(* Logix 5000 project; controller AMCI_5034_PTO_AM_Sample vendor 1 type 14 code 190 rev 37.11; software revision 37.00; part 2 of 3 *)
(* tags used below, declared in another part *)
   Move_type_0_Absolute_1_Relative : BOOL;   // 0=absolute 1=relative
   _0_normal_1_S_Curve_Acceleration : BOOL;
   _0_Triangular_1_Trapezoidal_S_Curve : BOOL;
   TargetVelocity : DINT;
   Acceleration : DINT;
   Deceleration : DINT;
   PC : BOOL;   // set when process complete
   motion_occurring : BOOL;
   Internal_Enable : BOOL;   // set when driver ready to receive motion command
(* AMCI_5034_PTO_AM_MAM, continued *)

ROUTINE Logic   (* ladder *)
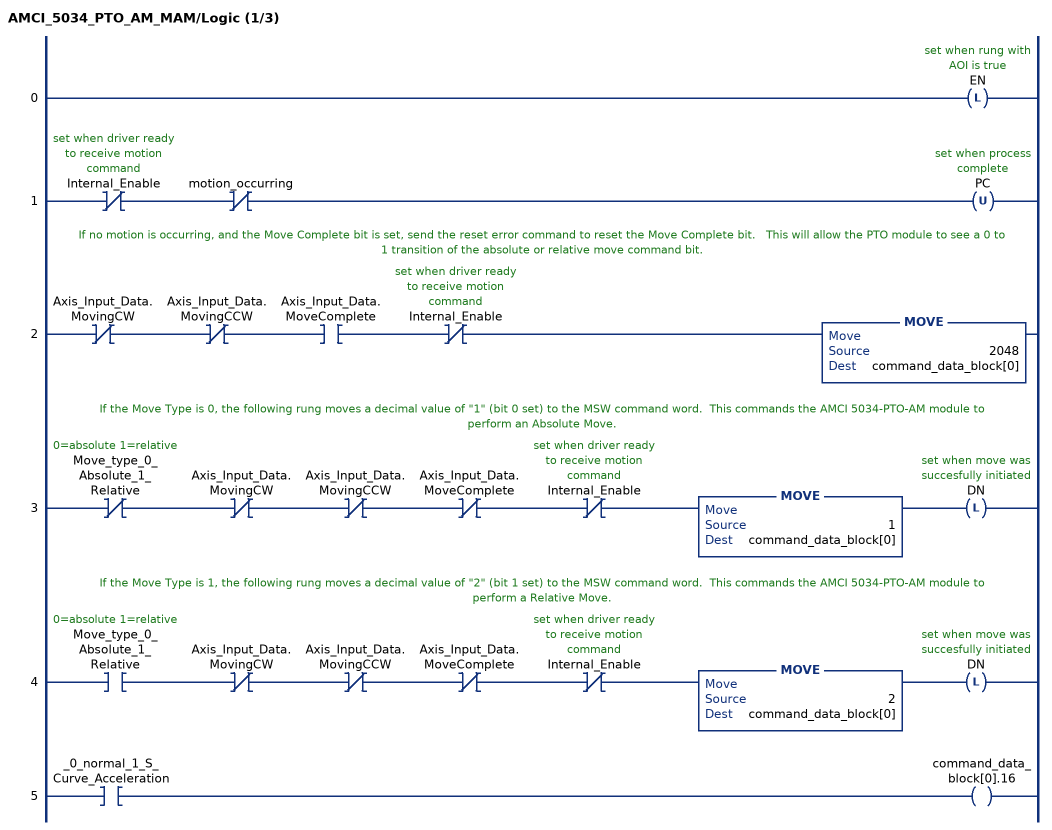
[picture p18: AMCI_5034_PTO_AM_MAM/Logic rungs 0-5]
   0: OTL(EN);
   1: XIO(Internal_Enable)XIO(motion_occurring)OTU(PC);
   // If no motion is occurring, and the Move Complete bit is set, send the reset error command to reset the Move Complete bit.   This will allow the PTO module to see a 0 to 1 transition of the absolute or relative move command bit.
   2: XIO(Axis_Input_Data.MovingCW)XIO(Axis_Input_Data.MovingCCW)XIC(Axis_Input_Data.MoveComplete)XIO(Internal_Enable)MOVE(2048,command_data_block[0]);
   // If the Move Type is 0, the following rung moves a decimal value of "1" (bit 0 set) to the MSW command word.  This commands the AMCI 5034-PTO-AM module to perform an Absolute Move.
   3: XIO(Move_type_0_Absolute_1_Relative)XIO(Axis_Input_Data.MovingCW)XIO(Axis_Input_Data.MovingCCW)XIO(Axis_Input_Data.MoveComplete)XIO(Internal_Enable)MOVE(1,command_data_block[0])OTL(DN);
   // If the Move Type is 1, the following rung moves a decimal value of "2" (bit 1 set) to the MSW command word.  This commands the AMCI 5034-PTO-AM module to perform a Relative Move.
   4: XIC(Move_type_0_Absolute_1_Relative)XIO(Axis_Input_Data.MovingCW)XIO(Axis_Input_Data.MovingCCW)XIO(Axis_Input_Data.MoveComplete)XIO(Internal_Enable)MOVE(2,command_data_block[0])OTL(DN);
   5: XIC(_0_normal_1_S_Curve_Acceleration)OTE(command_data_block[0].16);
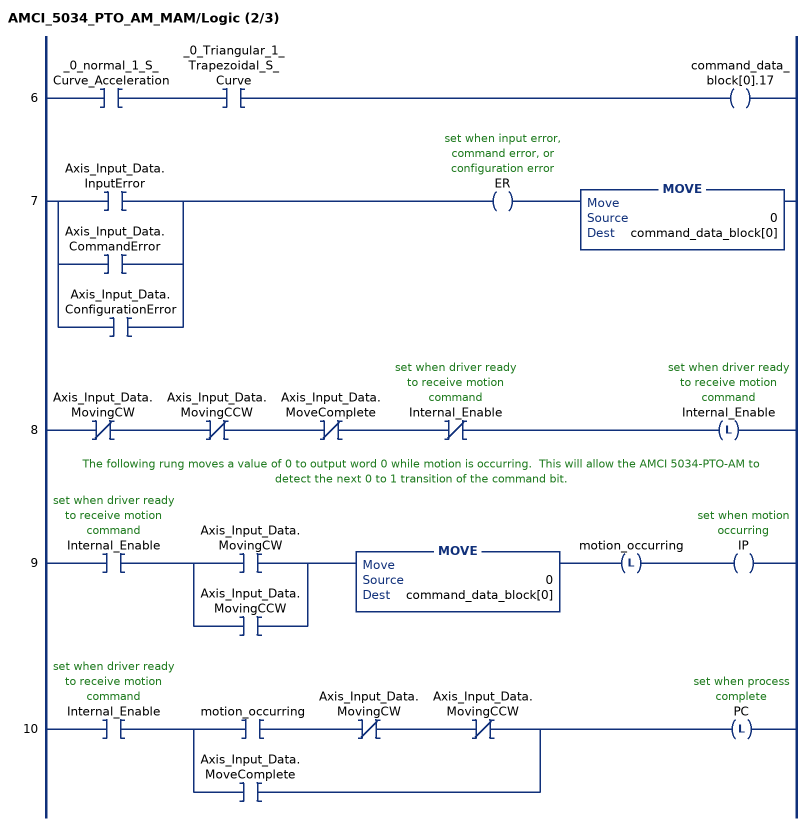
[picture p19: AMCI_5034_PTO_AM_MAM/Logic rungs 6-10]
   6: XIC(_0_normal_1_S_Curve_Acceleration)XIC(_0_Triangular_1_Trapezoidal_S_Curve)OTE(command_data_block[0].17);
   7: [XIC(Axis_Input_Data.InputError) ,XIC(Axis_Input_Data.CommandError) ,XIC(Axis_Input_Data.ConfigurationError) ]OTE(ER)MOVE(0,command_data_block[0]);
   8: XIO(Axis_Input_Data.MovingCW)XIO(Axis_Input_Data.MovingCCW)XIO(Axis_Input_Data.MoveComplete)XIO(Internal_Enable)OTL(Internal_Enable);
   // The following rung moves a value of 0 to output word 0 while motion is occurring.  This will allow the AMCI 5034-PTO-AM to detect the next 0 to 1 transition of the command bit.
   9: XIC(Internal_Enable)[XIC(Axis_Input_Data.MovingCW) ,XIC(Axis_Input_Data.MovingCCW) ]MOVE(0,command_data_block[0])OTL(motion_occurring)OTE(IP);
   10: XIC(Internal_Enable)[XIC(motion_occurring) XIO(Axis_Input_Data.MovingCW) XIO(Axis_Input_Data.MovingCCW) ,XIC(Axis_Input_Data.MoveComplete) ]OTL(PC);
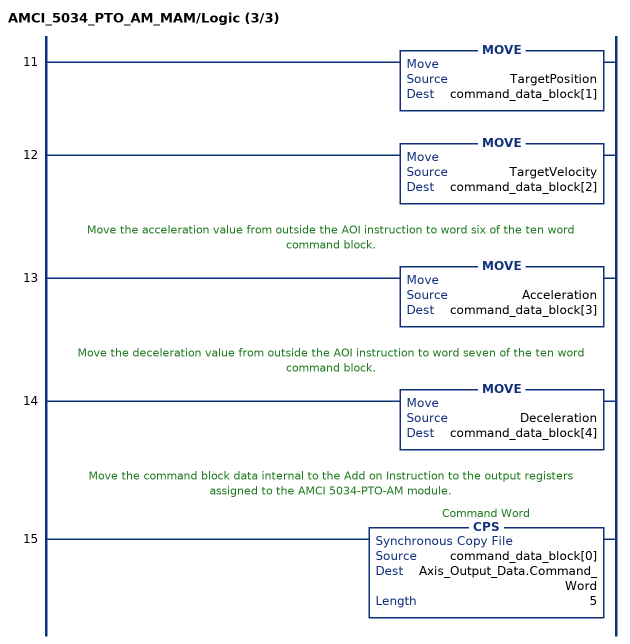
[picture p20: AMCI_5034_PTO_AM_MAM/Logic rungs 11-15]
   11: MOVE(TargetPosition,command_data_block[1]);
   12: MOVE(TargetVelocity,command_data_block[2]);
   // Move the acceleration value from outside the AOI instruction to word six of the ten word command block.
   13: MOVE(Acceleration,command_data_block[3]);
   // Move the deceleration value from outside the AOI instruction to word seven of the ten word command block.
   14: MOVE(Deceleration,command_data_block[4]);
   // Move the command block data internal to the Add on Instruction to the output registers assigned to the AMCI 5034-PTO-AM module.
   15: CPS(command_data_block[0],Axis_Output_Data.Command_Word,5);
END_ROUTINE
END_ADD_ON_INSTRUCTION

ADD_ON_INSTRUCTION AMCI_5034_PTO_AM_MRP   (* revision 1.0, vendor AMCI, ExecuteEnableInFalse *)
// AMCI Preset Position
// Revision note:
// 10/01/2025 Intial release
// Help:
// MOTION REDEFINE POSITION: Sets the Current Motor Position to the value in the Target Position field of the AOI.  This command will also reset the Position Invalid status bit.
// AXIS INPUT DATA:  Input data from the AMCI 5034-PTO-AM.   Uses the AMCI_5034_PTO_Input_Data User Defined Data Type.
// AXIS OUTPUT DATA; Output data from the AOI to the AMCI 5034-PTO-AM.    Uses the AMCI_5034_PTO_Output_Data User Defined Data Type.
// TARGET POSITION: Position to which the Motor Position is to be set.
// SAVE_IN_FLASH_0_NO_1_YES:   Saves the offset in the flash memory.    Only used on the SVXXXE2 units.  Must be zero on all other units.
// EN (Enable) Set when rung is true, Reset when rung is false
// DN (Done) Set when command is sent to the motion device.  Reset when the rung is false.
// ER (Error) Set when a command or input error failed to clear.  Reset when the rung is false.
VAR_IN_OUT
   Axis_Input_Data : AMCI_5034_PTO_AM_Input_Data; {required}
   Axis_Output_Data : AMCI_5034_PTO_AM_Output_Data; {required}
END_VAR
VAR_INPUT
   TargetPosition : DINT; {required}
END_VAR
VAR_OUTPUT
   EN : BOOL; {visible}   // set when rung with AOI is true
   DN : BOOL; {access Read Only, visible}   // set when preset motor position command sent to motion axis
   ER : BOOL; {access Read Only, visible}   // set when input, command, or configuraiton error
END_VAR
VAR
   command_data_block : DINT[5];
        [0]   // Command Bits MSW
        [1]   // Target Position
        [2]   // Upper Target Position
        [3]   // Lower Target Position
        [4]   // Upper Programmed Speed
END_VAR

ROUTINE EnableInFalse   (* ladder *)
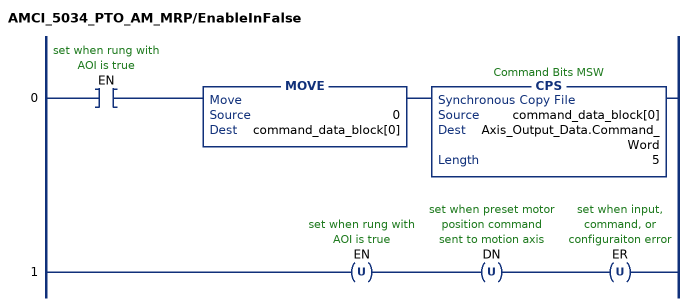
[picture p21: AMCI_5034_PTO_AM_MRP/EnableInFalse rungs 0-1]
   0: XIC(EN)MOVE(0,command_data_block[0])CPS(command_data_block[0],Axis_Output_Data.Command_Word,5);
   1: OTU(EN)OTU(DN)OTU(ER);
END_ROUTINE

ROUTINE Logic   (* ladder *)
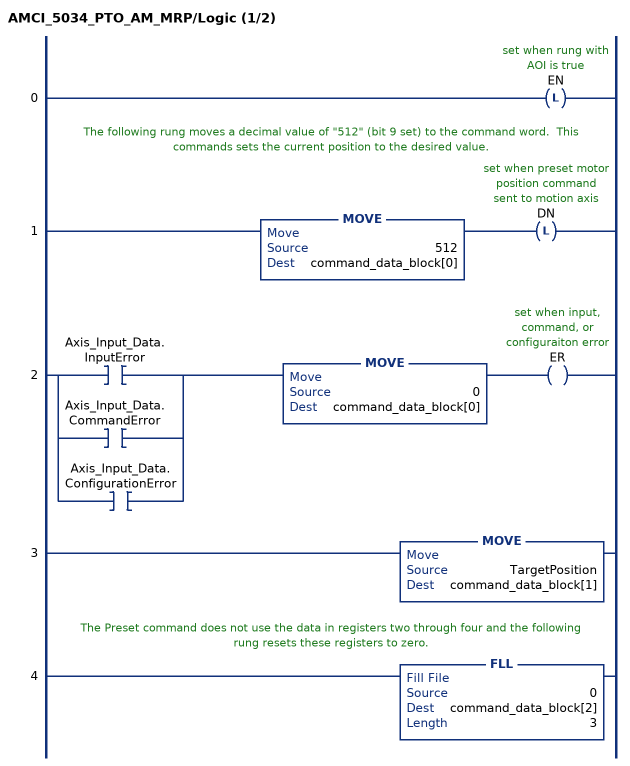
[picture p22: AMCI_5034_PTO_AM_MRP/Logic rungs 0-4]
   0: OTL(EN);
   // The following rung moves a decimal value of "512" (bit 9 set) to the command word.  This commands sets the current position to the desired value.
   1: MOVE(512,command_data_block[0])OTL(DN);
   2: [XIC(Axis_Input_Data.InputError) ,XIC(Axis_Input_Data.CommandError) ,XIC(Axis_Input_Data.ConfigurationError) ]MOVE(0,command_data_block[0])OTE(ER);
   3: MOVE(TargetPosition,command_data_block[1]);
   // The Preset command does not use the data in registers two through four and the following rung resets these registers to zero.
   4: FLL(0,command_data_block[2],3);
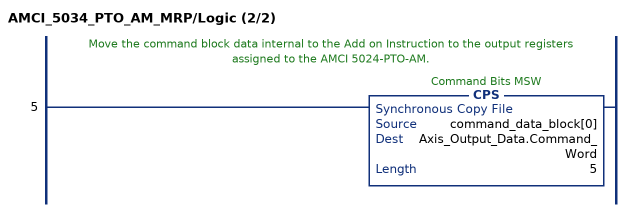
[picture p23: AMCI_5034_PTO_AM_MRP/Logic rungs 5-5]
   // Move the command block data internal to the Add on Instruction to the output registers assigned to the AMCI 5024-PTO-AM.
   5: CPS(command_data_block[0],Axis_Output_Data.Command_Word,5);
END_ROUTINE
END_ADD_ON_INSTRUCTION

ADD_ON_INSTRUCTION AMCI_5034_PTO_AM_Preset_Encoder   (* revision 1.0, vendor AMCI, ExecuteEnableInFalse *)
// Revision note:
// 10/01/2025 initial release
// Help:
// PRESET_ENCODER: Preset Encoder Position to the Target Position value.
// AXIS INPUT DATA:  Input data from the AMCI 5034-PTO-AM.   Uses the AMCI_5034_PTO_Input_Data User Defined Data Type.
// AXIS OUTPUT DATA; Output data from the AOI to the AMCI 5034-PTO-AM.    Uses the AMCI_5034_PTO_Output_Data User Defined Data Type.
// TARGETPOSITION: Position to which the Encoder Position is to be set.
// EN (Enable) Set when rung is true, Reset when rung is false
// DN (Done) Set when command is sent to the motion device.  Reset when the rung is false.
// ER (Error) Set when a command or input error failed to clear.  Reset when the rung is false.
VAR_IN_OUT
   Axis_Input_Data : AMCI_5034_PTO_AM_Input_Data; {required}
   Axis_Output_Data : AMCI_5034_PTO_AM_Output_Data; {required}
END_VAR
VAR_INPUT
   TargetPosition : DINT; {required}
END_VAR
VAR_OUTPUT
   EN : BOOL; {visible}   // set when rung with AOI is true
   DN : BOOL; {access Read Only, visible}   // set when preset motor position command sent to motion axis
   ER : BOOL; {access Read Only, visible}   // set when input, command, or configuraiton error
END_VAR
VAR
   command_data_block : DINT[5];
        [0]   // Command Bits MSW
        [1]   // Target Position
        [2]   // Upper Target Position
        [3]   // Lower Target Position
        [4]   // Upper Programmed Speed
END_VAR

ROUTINE EnableInFalse   (* ladder *)
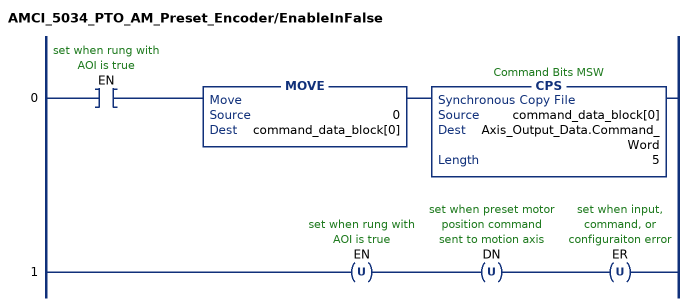
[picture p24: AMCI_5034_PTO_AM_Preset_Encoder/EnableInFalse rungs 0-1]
   0: XIC(EN)MOVE(0,command_data_block[0])CPS(command_data_block[0],Axis_Output_Data.Command_Word,5);
   1: OTU(EN)OTU(DN)OTU(ER);
END_ROUTINE

ROUTINE Logic   (* ladder *)
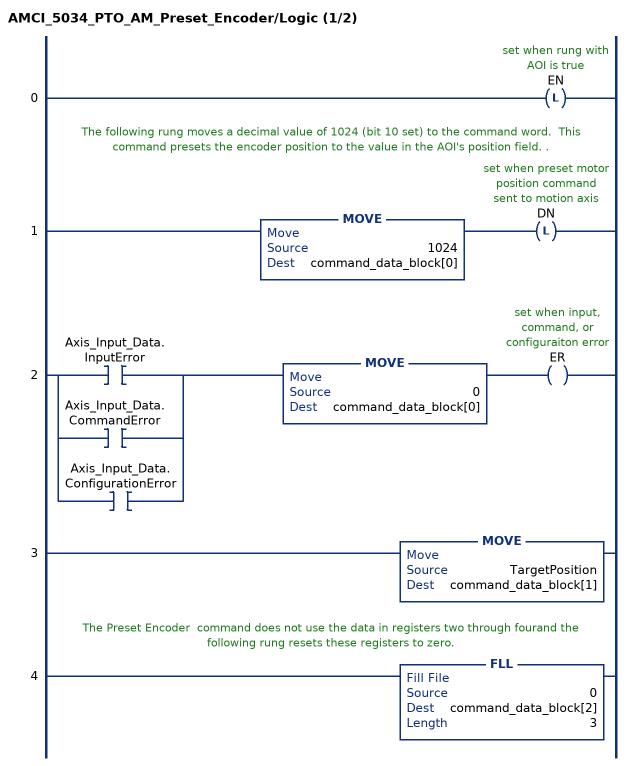
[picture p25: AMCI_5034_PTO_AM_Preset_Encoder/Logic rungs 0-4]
   0: OTL(EN);
   // The following rung moves a decimal value of 1024 (bit 10 set) to the command word.  This command presets the encoder position to the value in the AOI's position field. .
   1: MOVE(1024,command_data_block[0])OTL(DN);
   2: [XIC(Axis_Input_Data.InputError) ,XIC(Axis_Input_Data.CommandError) ,XIC(Axis_Input_Data.ConfigurationError) ]MOVE(0,command_data_block[0])OTE(ER);
   3: MOVE(TargetPosition,command_data_block[1]);
   // The Preset Encoder  command does not use the data in registers two through fourand the following rung resets these registers to zero.
   4: FLL(0,command_data_block[2],3);
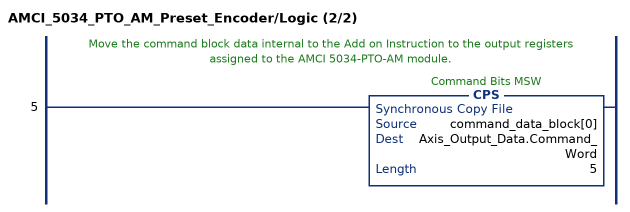
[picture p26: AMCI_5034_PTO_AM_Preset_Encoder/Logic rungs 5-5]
   // Move the command block data internal to the Add on Instruction to the output registers assigned to the AMCI 5034-PTO-AM module.
   5: CPS(command_data_block[0],Axis_Output_Data.Command_Word,5);
END_ROUTINE
END_ADD_ON_INSTRUCTION

ADD_ON_INSTRUCTION AMCI_5034_PTO_AM_Prog_Min_Reg_Dist   (* revision 1.0, vendor AMCI, ExecuteEnableInFalse *)
// AMCI Program Minimum Registration Distance
// Revision note:
// 10/01/2025 Intial release
// Help:
// AXIS INPUT DATA:  Input data from the AMCI 5034-PTO-AM.   Uses the AMCI_5034_PTO_Input_Data User Defined Data Type.
// AXIS OUTPUT DATA; Output data from the AOI to the AMCI 5034-PTO-AM.    Uses the AMCI_5034_PTO_Output_Data User Defined Data Type.
// TARGETPOSITION: The number of steps that must be output by the PTO module before it will start looking for the registration input.
// EN (Enable) Set when rung is true, Reset when rung is false
// DN (Done) Set when command is sent to the PTO module.  Reset when the rung is false.
// ER (Error) Set when a command, input error, or configuation error.   Reset when the rung is false.
VAR_IN_OUT
   Axis_Input_Data : AMCI_5034_PTO_AM_Input_Data; {required}
   Axis_Output_Data : AMCI_5034_PTO_AM_Output_Data; {required}
END_VAR
VAR_INPUT
   Minimum_Registration_Distance : DINT; {required}
END_VAR
VAR_OUTPUT
   EN : BOOL; {visible}   // set when rung with AOI is true
   DN : BOOL; {access Read Only, visible}   // set when mnimum registration distance has been programmed
   ER : BOOL; {access Read Only, visible}   // set when input, command, or configuraiton error
END_VAR
VAR
   command_data_block : DINT[5];
        [0]   // Command Bits MSW
        [1]   // Target Position
        [2]   // Upper Target Position
        [3]   // Lower Target Position
        [4]   // Upper Programmed Speed
END_VAR

ROUTINE EnableInFalse   (* ladder *)
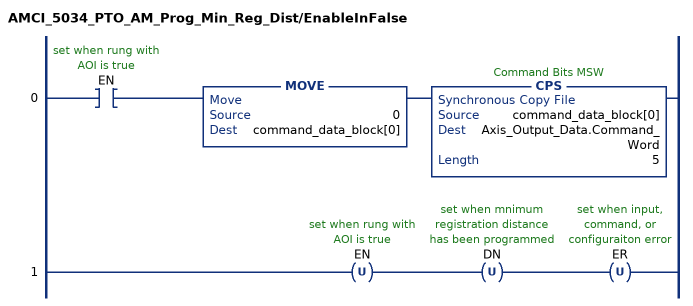
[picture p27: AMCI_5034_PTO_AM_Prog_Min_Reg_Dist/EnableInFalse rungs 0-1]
   0: XIC(EN)MOVE(0,command_data_block[0])CPS(command_data_block[0],Axis_Output_Data.Command_Word,5);
   1: OTU(EN)OTU(DN)OTU(ER);
END_ROUTINE

ROUTINE Logic   (* ladder *)
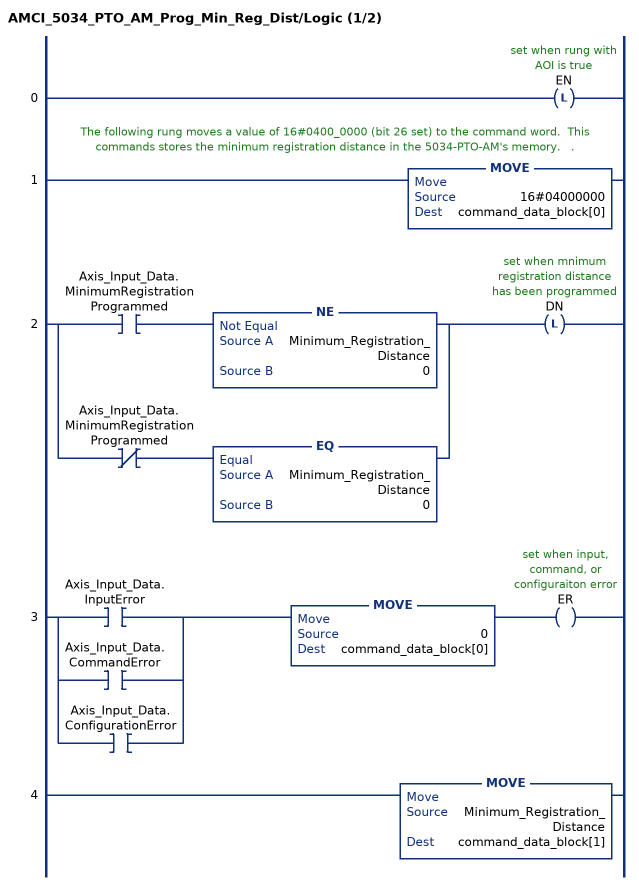
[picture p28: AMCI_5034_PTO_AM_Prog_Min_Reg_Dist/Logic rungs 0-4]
   0: OTL(EN);
   // The following rung moves a value of 16#0400_0000 (bit 26 set) to the command word.  This commands stores the minimum registration distance in the 5034-PTO-AM's memory.   .
   1: MOVE(16#04000000,command_data_block[0]);
   2: [XIC(Axis_Input_Data.MinimumRegistrationProgrammed) NE(Minimum_Registration_Distance,0) ,XIO(Axis_Input_Data.MinimumRegistrationProgrammed) EQ(Minimum_Registration_Distance,0) ]OTL(DN);
   3: [XIC(Axis_Input_Data.InputError) ,XIC(Axis_Input_Data.CommandError) ,XIC(Axis_Input_Data.ConfigurationError) ]MOVE(0,command_data_block[0])OTE(ER);
   4: MOVE(Minimum_Registration_Distance,command_data_block[1]);
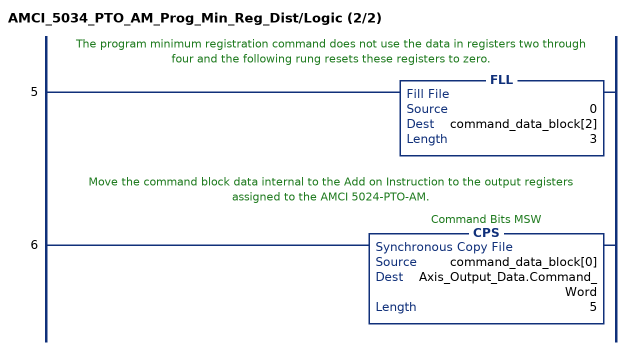
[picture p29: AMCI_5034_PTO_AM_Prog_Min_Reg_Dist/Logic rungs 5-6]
   // The program minimum registration command does not use the data in registers two through four and the following rung resets these registers to zero.
   5: FLL(0,command_data_block[2],3);
   // Move the command block data internal to the Add on Instruction to the output registers assigned to the AMCI 5024-PTO-AM.
   6: CPS(command_data_block[0],Axis_Output_Data.Command_Word,5);
END_ROUTINE
END_ADD_ON_INSTRUCTION

ADD_ON_INSTRUCTION AMCI_5034_PTO_AM_Program_Blend_Move   (* revision 0.0, ExecuteEnableInFalse *)
// Revision note:
// 10/01/2025 initial release
// Help:
// Programs up to 16 segments of a blend move.
// AXIS INPUT DATA:  Input data from the AMCI 5034-PTO-AM.   Uses the AMCI_5034_PTO_Input_Data User Defined Data Type.
// AXIS OUTPUT DATA; Output data from the AOI to the AMCI 5034-PTO-AM.    Uses the AMCI_5034_PTO_Output_Data User Defined Data Type.
// NUMBER_OF_SEGMENTS: Defines the number of segments in the blend move.   Range of 2 to 16.
// FINAL_MOVE_DECELERATION: Defines the deceleration from the last sement to rest.
// SEGMENT_X_DISTANCE: The relative move distance of each of the segments.
// SEGMENT_X_TARGETVELOCITY: The speed of the segment.
// SEGMENT_X_ ACCELERATION_DECELERATION: The value to accelerate or decelerate from one segment to the next segment.
// EN: Set whe the rung with the Program Blend AOI is receiving power.
// ER: Set when there is a Command Error, Configuation Error, Input Error, or Invalid Profile Error.
// IP: Set when each segment of the blend profile is being programmed.
// BLEND_MOVE_PROGRAMMED: Set when all of the segments of the blend profile have been programmed.
VAR_IN_OUT
   Axis_Input_Data : AMCI_5034_PTO_AM_Input_Data; {required}
   Axis_Output_Data : AMCI_5034_PTO_AM_Output_Data; {required}
END_VAR
VAR_INPUT
   Number_of_Segments : DINT; {required}
   Acceleration_Type_segments_1_to_16 : DINT;
   Final_Move_Deceleration : DINT; {required}
   Segment_1_Distance : DINT; {required}
   Segment_1_TargetVelocity : DINT; {required}
   Segment_1_Acceleration_Deceleration : DINT; {required}
   Segment_2_Distance : DINT; {required}
   Segment_2_TargetVelocity : DINT; {required}
   Segment_2_Acceleration_Deceleration : DINT; {required}
   Segment_3_Distance : DINT; {required}
   Segment_3_TargetVelocity : DINT; {required}
   Segment_3_Acceleration_Deceleration : DINT; {required}
   Segment_4_Distance : DINT; {required}
   Segment_4_TargetVelocity : DINT; {required}
   Segment_4_Acceleration_Deceleration : DINT; {required}
   Segment_5_Distance : DINT; {required}
   Segment_5_TargetVelocity : DINT; {required}
   Segment_5_Acceleration_Deceleration : DINT; {required}
   Segment_6_Distance : DINT; {required}
   Segment_6_TargetVelocity : DINT; {required}
   Segment_6_Acceleration_Deceleration : DINT; {required}
   Segment_7_Distance : DINT; {required}
   Segment_7_TargetVelocity : DINT; {required}
   Segment_7_Acceleration_Deceleration : DINT; {required}
   Segment_8_Distance : DINT; {required}
   Segment_8_TargetVelocity : DINT; {required}
   Segment_8_Acceleration_Deceleration : DINT; {required}
   Segment_9_Distance : DINT; {required}
   Segment_9_TargetVelocity : DINT; {required}
   Segment_9_Acceleration_Deceleration : DINT; {required}
   Segment_10_Distance : DINT; {required}
   Segment_10_TargetVelocity : DINT; {required}
   Segment_10_Acceleration_Deceleration : DINT; {required}
   Segment_11_Distance : DINT; {required}
   Segment_11_TargetVelocity : DINT; {required}
   Segment_11_Acceleration_Deceleration : DINT; {required}
   Segment_12_Distance : DINT; {required}
   Segment_12_TargetVelocity : DINT; {required}
   Segment_12_Acceleration_Deceleration : DINT; {required}
   Segment_13_Distance : DINT; {required}
   Segment_13_TargetVelocity : DINT; {required}
   Segment_13_Acceleration_Deceleration : DINT; {required}
   Segment_14_Distance : DINT; {required}
   Segment_14_TargetVelocity : DINT; {required}
   Segment_14_Acceleration_Deceleration : DINT; {required}
   Segment_15_Distance : DINT; {required}
   Segment_15_TargetVelocity : DINT; {required}
   Segment_15_Acceleration_Deceleration : DINT; {required}
   Segment_16_Distance : DINT; {required}
   Segment_16_TargetVelocity : DINT; {required}
   Segment_16_Acceleration_Deceleration : DINT; {required}
END_VAR
VAR_OUTPUT
   EN : BOOL; {visible}   // set when rung with AOI is true
   ER : BOOL; {visible}   // set when invalid profile, input error, command error, or configuration error
   IP : BOOL; {visible}   // Set when Blend Move is being programmed
   Blend_Move_Programmed : BOOL; {access Read Only, visible}
END_VAR
VAR
   command_data_block : DINT[5];
   Blend_Move_setup : DINT[5];
   Blend_Move_counter : COUNTER;
END_VAR

ROUTINE EnableInFalse   (* ladder *)
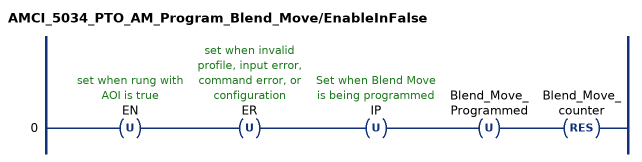
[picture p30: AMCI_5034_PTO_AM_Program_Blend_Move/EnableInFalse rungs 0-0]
   0: OTU(EN)OTU(ER)OTU(IP)OTU(Blend_Move_Programmed)RES(Blend_Move_counter);
END_ROUTINE

ROUTINE Logic   (* ladder *)
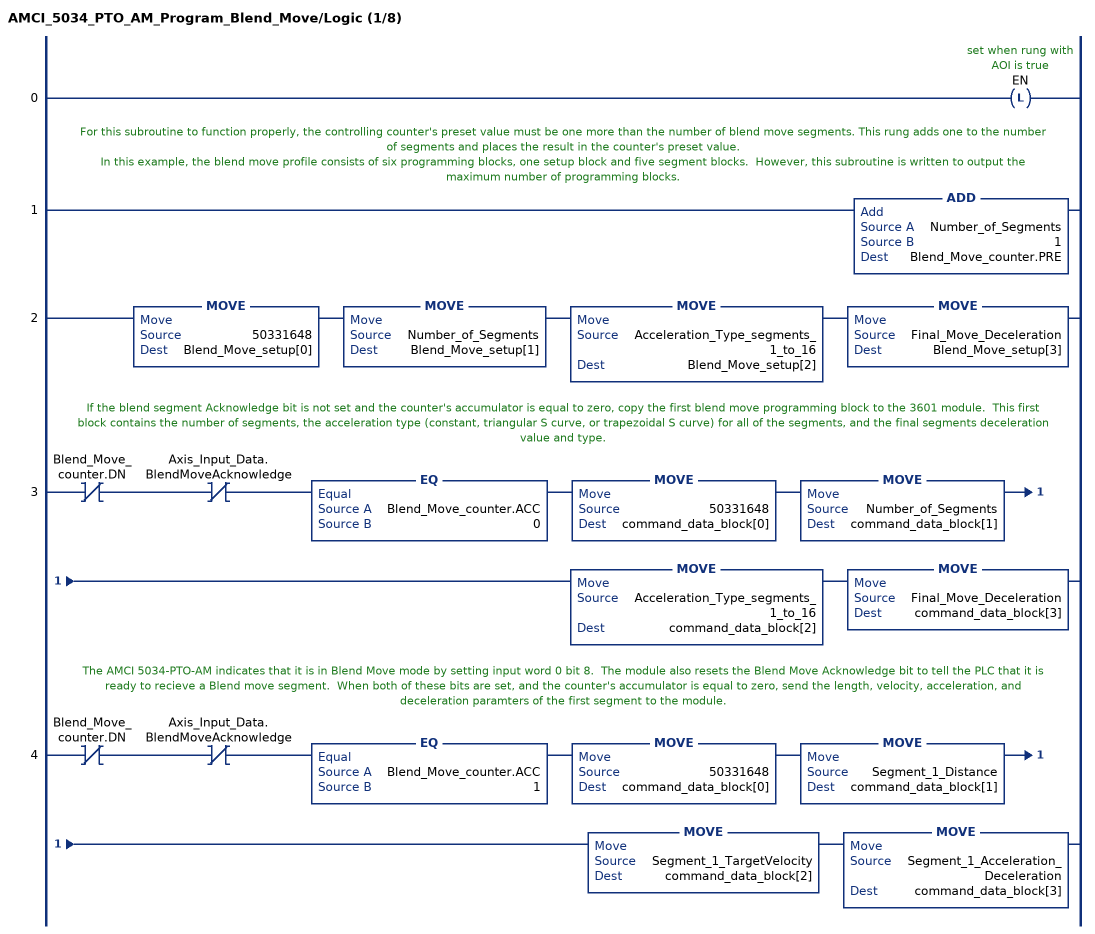
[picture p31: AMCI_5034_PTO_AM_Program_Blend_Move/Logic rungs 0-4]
   0: OTL(EN);
   // For this subroutine to function properly, the controlling counter's preset value must be one more than the number of blend move segments. This rung adds one to the number of segments and places the result in the counter's preset value.
   // In this example, the blend move profile consists of six programming blocks, one setup block and five segment blocks.  However, this subroutine is written to output the maximum number of programming blocks.
   1: ADD(Number_of_Segments,1,Blend_Move_counter.PRE);
   2: MOVE(50331648,Blend_Move_setup[0])MOVE(Number_of_Segments,Blend_Move_setup[1])MOVE(Acceleration_Type_segments_1_to_16,Blend_Move_setup[2])MOVE(Final_Move_Deceleration,Blend_Move_setup[3]);
   // If the blend segment Acknowledge bit is not set and the counter's accumulator is equal to zero, copy the first blend move programming block to the 3601 module.  This first block contains the number of segments, the acceleration type (constant, triangular S curve, or trapezoidal S curve) for all of the segments, and the final segments deceleration value and type.
   3: XIO(Blend_Move_counter.DN)XIO(Axis_Input_Data.BlendMoveAcknowledge)EQ(Blend_Move_counter.ACC,0)MOVE(50331648,command_data_block[0])MOVE(Number_of_Segments,command_data_block[1])MOVE(Acceleration_Type_segments_1_to_16,command_data_block[2])MOVE(Final_Move_Deceleration,command_data_block[3]);
   // The AMCI 5034-PTO-AM indicates that it is in Blend Move mode by setting input word 0 bit 8.  The module also resets the Blend Move Acknowledge bit to tell the PLC that it is ready to recieve a Blend move segment.  When both of these bits are set, and the counter's accumulator is equal to zero, send the length, velocity, acceleration, and deceleration paramters of the first segment to the module.
   4: XIO(Blend_Move_counter.DN)XIO(Axis_Input_Data.BlendMoveAcknowledge)EQ(Blend_Move_counter.ACC,1)MOVE(50331648,command_data_block[0])MOVE(Segment_1_Distance,command_data_block[1])MOVE(Segment_1_TargetVelocity,command_data_block[2])MOVE(Segment_1_Acceleration_Deceleration,command_data_block[3]);
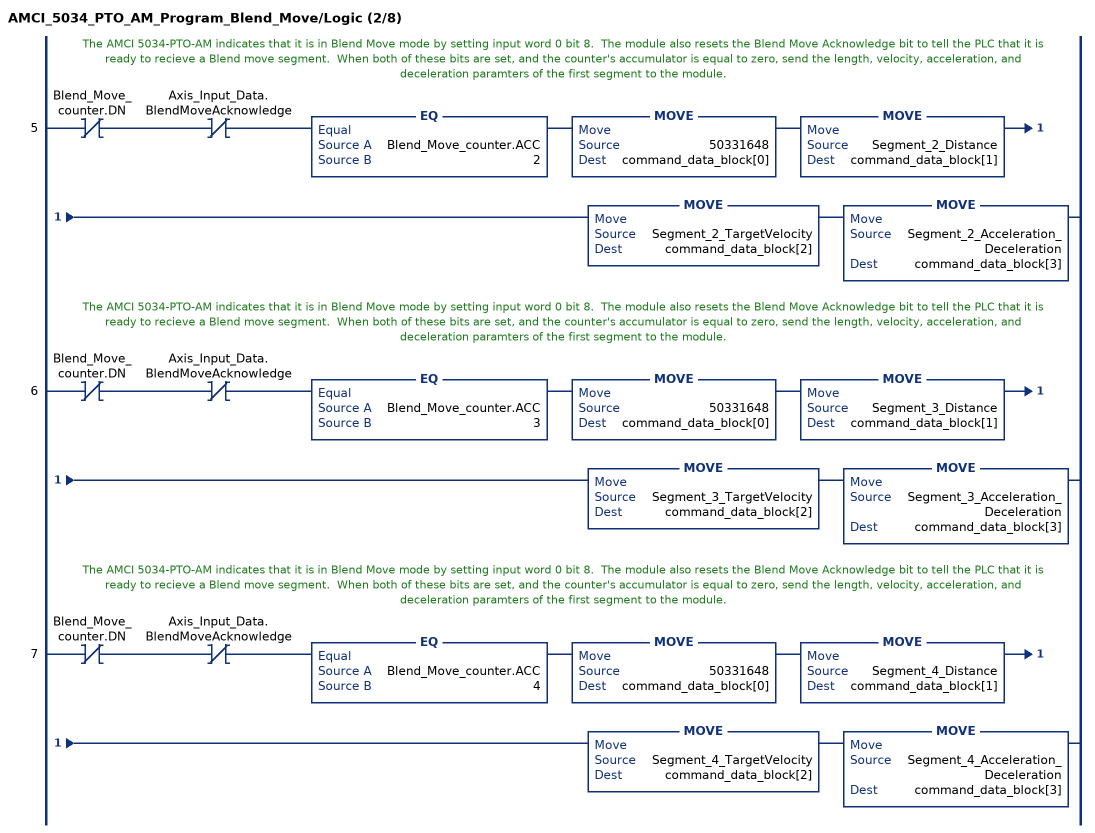
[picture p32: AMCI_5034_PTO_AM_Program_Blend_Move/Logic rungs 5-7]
   // The AMCI 5034-PTO-AM indicates that it is in Blend Move mode by setting input word 0 bit 8.  The module also resets the Blend Move Acknowledge bit to tell the PLC that it is ready to recieve a Blend move segment.  When both of these bits are set, and the counter's accumulator is equal to zero, send the length, velocity, acceleration, and deceleration paramters of the first segment to the module.
   5: XIO(Blend_Move_counter.DN)XIO(Axis_Input_Data.BlendMoveAcknowledge)EQ(Blend_Move_counter.ACC,2)MOVE(50331648,command_data_block[0])MOVE(Segment_2_Distance,command_data_block[1])MOVE(Segment_2_TargetVelocity,command_data_block[2])MOVE(Segment_2_Acceleration_Deceleration,command_data_block[3]);
   // The AMCI 5034-PTO-AM indicates that it is in Blend Move mode by setting input word 0 bit 8.  The module also resets the Blend Move Acknowledge bit to tell the PLC that it is ready to recieve a Blend move segment.  When both of these bits are set, and the counter's accumulator is equal to zero, send the length, velocity, acceleration, and deceleration paramters of the first segment to the module.
   6: XIO(Blend_Move_counter.DN)XIO(Axis_Input_Data.BlendMoveAcknowledge)EQ(Blend_Move_counter.ACC,3)MOVE(50331648,command_data_block[0])MOVE(Segment_3_Distance,command_data_block[1])MOVE(Segment_3_TargetVelocity,command_data_block[2])MOVE(Segment_3_Acceleration_Deceleration,command_data_block[3]);
   // The AMCI 5034-PTO-AM indicates that it is in Blend Move mode by setting input word 0 bit 8.  The module also resets the Blend Move Acknowledge bit to tell the PLC that it is ready to recieve a Blend move segment.  When both of these bits are set, and the counter's accumulator is equal to zero, send the length, velocity, acceleration, and deceleration paramters of the first segment to the module.
   7: XIO(Blend_Move_counter.DN)XIO(Axis_Input_Data.BlendMoveAcknowledge)EQ(Blend_Move_counter.ACC,4)MOVE(50331648,command_data_block[0])MOVE(Segment_4_Distance,command_data_block[1])MOVE(Segment_4_TargetVelocity,command_data_block[2])MOVE(Segment_4_Acceleration_Deceleration,command_data_block[3]);
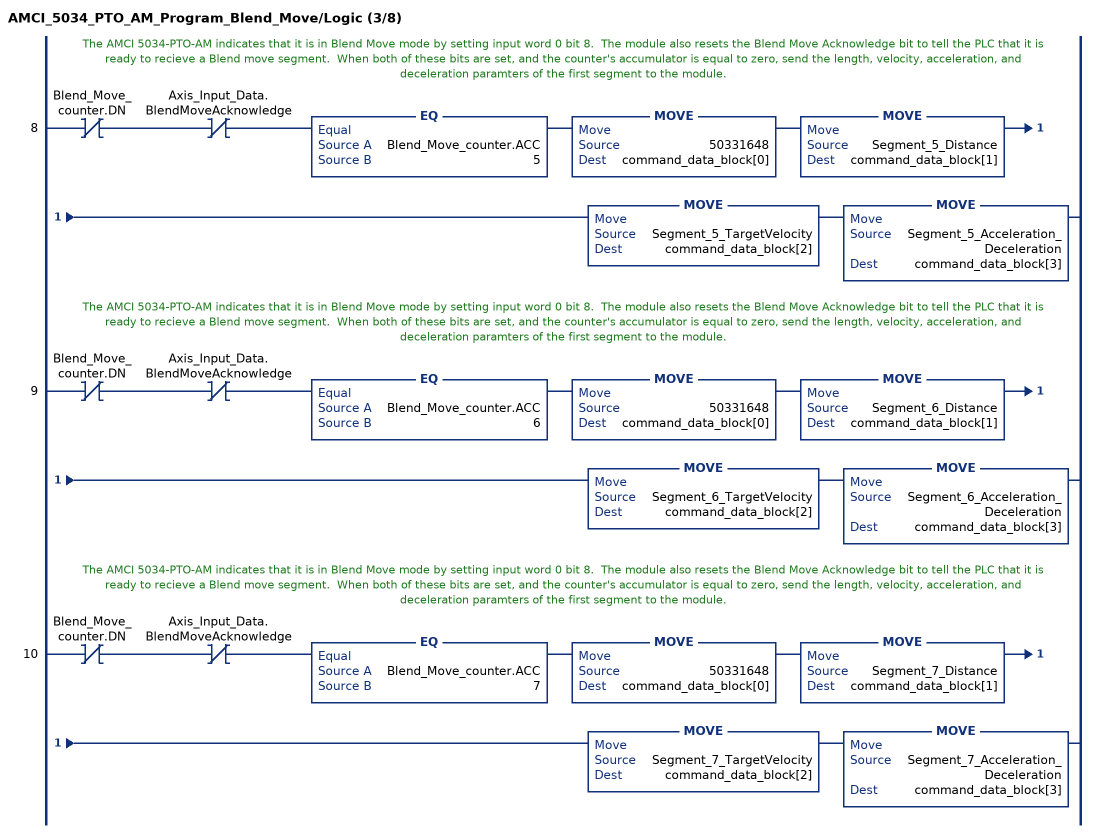
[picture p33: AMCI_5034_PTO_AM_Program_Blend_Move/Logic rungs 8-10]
   // The AMCI 5034-PTO-AM indicates that it is in Blend Move mode by setting input word 0 bit 8.  The module also resets the Blend Move Acknowledge bit to tell the PLC that it is ready to recieve a Blend move segment.  When both of these bits are set, and the counter's accumulator is equal to zero, send the length, velocity, acceleration, and deceleration paramters of the first segment to the module.
   8: XIO(Blend_Move_counter.DN)XIO(Axis_Input_Data.BlendMoveAcknowledge)EQ(Blend_Move_counter.ACC,5)MOVE(50331648,command_data_block[0])MOVE(Segment_5_Distance,command_data_block[1])MOVE(Segment_5_TargetVelocity,command_data_block[2])MOVE(Segment_5_Acceleration_Deceleration,command_data_block[3]);
   // The AMCI 5034-PTO-AM indicates that it is in Blend Move mode by setting input word 0 bit 8.  The module also resets the Blend Move Acknowledge bit to tell the PLC that it is ready to recieve a Blend move segment.  When both of these bits are set, and the counter's accumulator is equal to zero, send the length, velocity, acceleration, and deceleration paramters of the first segment to the module.
   9: XIO(Blend_Move_counter.DN)XIO(Axis_Input_Data.BlendMoveAcknowledge)EQ(Blend_Move_counter.ACC,6)MOVE(50331648,command_data_block[0])MOVE(Segment_6_Distance,command_data_block[1])MOVE(Segment_6_TargetVelocity,command_data_block[2])MOVE(Segment_6_Acceleration_Deceleration,command_data_block[3]);
   // The AMCI 5034-PTO-AM indicates that it is in Blend Move mode by setting input word 0 bit 8.  The module also resets the Blend Move Acknowledge bit to tell the PLC that it is ready to recieve a Blend move segment.  When both of these bits are set, and the counter's accumulator is equal to zero, send the length, velocity, acceleration, and deceleration paramters of the first segment to the module.
   10: XIO(Blend_Move_counter.DN)XIO(Axis_Input_Data.BlendMoveAcknowledge)EQ(Blend_Move_counter.ACC,7)MOVE(50331648,command_data_block[0])MOVE(Segment_7_Distance,command_data_block[1])MOVE(Segment_7_TargetVelocity,command_data_block[2])MOVE(Segment_7_Acceleration_Deceleration,command_data_block[3]);
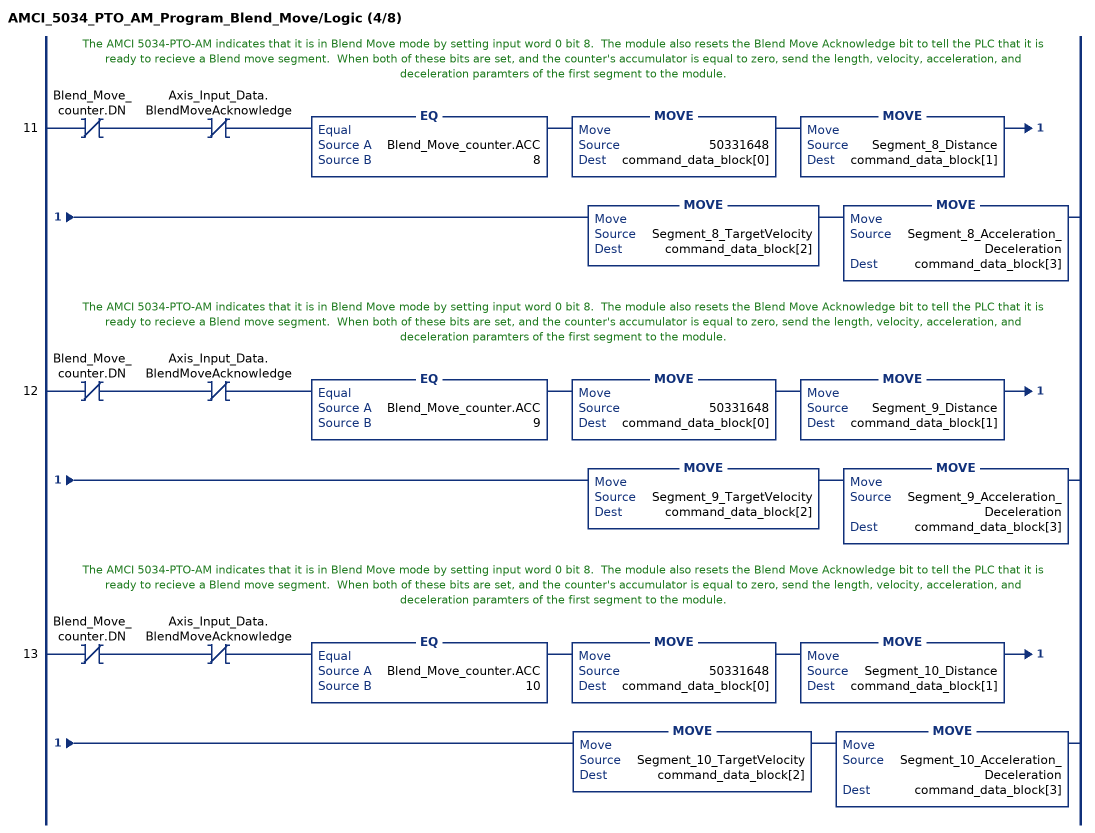
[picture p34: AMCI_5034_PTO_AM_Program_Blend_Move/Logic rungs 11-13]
   // The AMCI 5034-PTO-AM indicates that it is in Blend Move mode by setting input word 0 bit 8.  The module also resets the Blend Move Acknowledge bit to tell the PLC that it is ready to recieve a Blend move segment.  When both of these bits are set, and the counter's accumulator is equal to zero, send the length, velocity, acceleration, and deceleration paramters of the first segment to the module.
   11: XIO(Blend_Move_counter.DN)XIO(Axis_Input_Data.BlendMoveAcknowledge)EQ(Blend_Move_counter.ACC,8)MOVE(50331648,command_data_block[0])MOVE(Segment_8_Distance,command_data_block[1])MOVE(Segment_8_TargetVelocity,command_data_block[2])MOVE(Segment_8_Acceleration_Deceleration,command_data_block[3]);
   // The AMCI 5034-PTO-AM indicates that it is in Blend Move mode by setting input word 0 bit 8.  The module also resets the Blend Move Acknowledge bit to tell the PLC that it is ready to recieve a Blend move segment.  When both of these bits are set, and the counter's accumulator is equal to zero, send the length, velocity, acceleration, and deceleration paramters of the first segment to the module.
   12: XIO(Blend_Move_counter.DN)XIO(Axis_Input_Data.BlendMoveAcknowledge)EQ(Blend_Move_counter.ACC,9)MOVE(50331648,command_data_block[0])MOVE(Segment_9_Distance,command_data_block[1])MOVE(Segment_9_TargetVelocity,command_data_block[2])MOVE(Segment_9_Acceleration_Deceleration,command_data_block[3]);
   // The AMCI 5034-PTO-AM indicates that it is in Blend Move mode by setting input word 0 bit 8.  The module also resets the Blend Move Acknowledge bit to tell the PLC that it is ready to recieve a Blend move segment.  When both of these bits are set, and the counter's accumulator is equal to zero, send the length, velocity, acceleration, and deceleration paramters of the first segment to the module.
   13: XIO(Blend_Move_counter.DN)XIO(Axis_Input_Data.BlendMoveAcknowledge)EQ(Blend_Move_counter.ACC,10)MOVE(50331648,command_data_block[0])MOVE(Segment_10_Distance,command_data_block[1])MOVE(Segment_10_TargetVelocity,command_data_block[2])MOVE(Segment_10_Acceleration_Deceleration,command_data_block[3]);
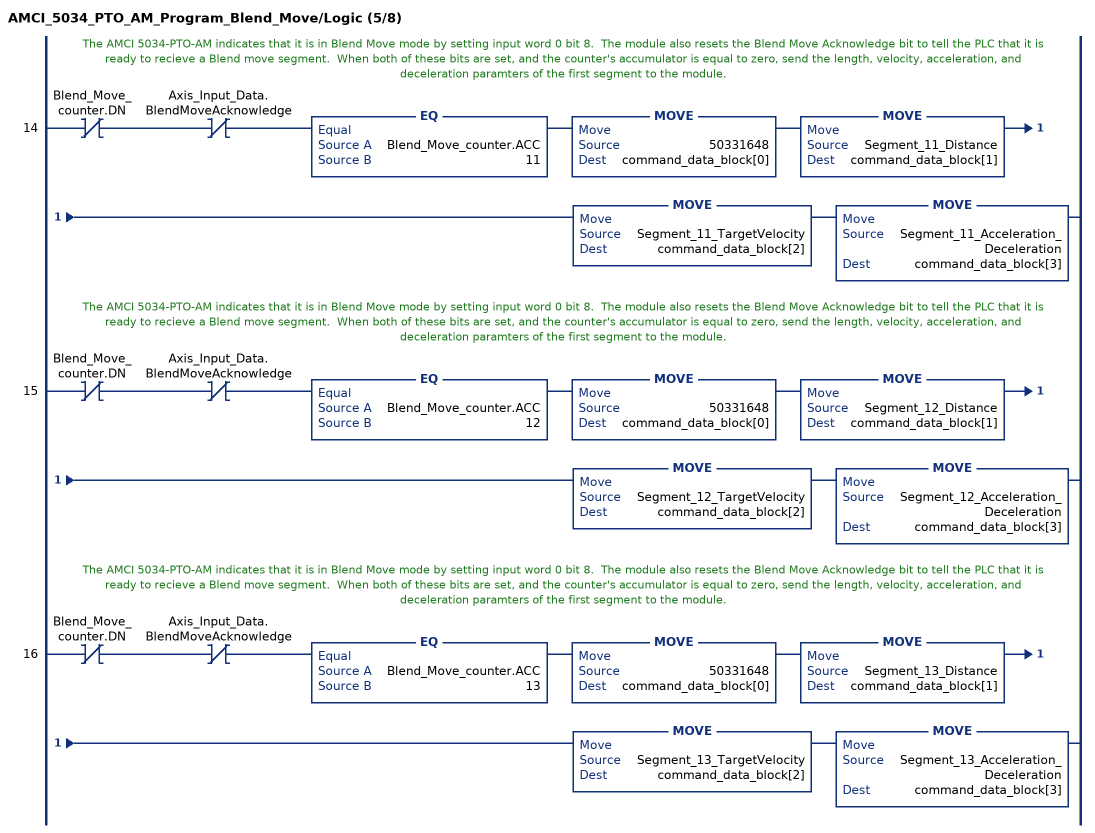
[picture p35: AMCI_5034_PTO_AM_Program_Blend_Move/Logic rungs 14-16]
   // The AMCI 5034-PTO-AM indicates that it is in Blend Move mode by setting input word 0 bit 8.  The module also resets the Blend Move Acknowledge bit to tell the PLC that it is ready to recieve a Blend move segment.  When both of these bits are set, and the counter's accumulator is equal to zero, send the length, velocity, acceleration, and deceleration paramters of the first segment to the module.
   14: XIO(Blend_Move_counter.DN)XIO(Axis_Input_Data.BlendMoveAcknowledge)EQ(Blend_Move_counter.ACC,11)MOVE(50331648,command_data_block[0])MOVE(Segment_11_Distance,command_data_block[1])MOVE(Segment_11_TargetVelocity,command_data_block[2])MOVE(Segment_11_Acceleration_Deceleration,command_data_block[3]);
   // The AMCI 5034-PTO-AM indicates that it is in Blend Move mode by setting input word 0 bit 8.  The module also resets the Blend Move Acknowledge bit to tell the PLC that it is ready to recieve a Blend move segment.  When both of these bits are set, and the counter's accumulator is equal to zero, send the length, velocity, acceleration, and deceleration paramters of the first segment to the module.
   15: XIO(Blend_Move_counter.DN)XIO(Axis_Input_Data.BlendMoveAcknowledge)EQ(Blend_Move_counter.ACC,12)MOVE(50331648,command_data_block[0])MOVE(Segment_12_Distance,command_data_block[1])MOVE(Segment_12_TargetVelocity,command_data_block[2])MOVE(Segment_12_Acceleration_Deceleration,command_data_block[3]);
   // The AMCI 5034-PTO-AM indicates that it is in Blend Move mode by setting input word 0 bit 8.  The module also resets the Blend Move Acknowledge bit to tell the PLC that it is ready to recieve a Blend move segment.  When both of these bits are set, and the counter's accumulator is equal to zero, send the length, velocity, acceleration, and deceleration paramters of the first segment to the module.
   16: XIO(Blend_Move_counter.DN)XIO(Axis_Input_Data.BlendMoveAcknowledge)EQ(Blend_Move_counter.ACC,13)MOVE(50331648,command_data_block[0])MOVE(Segment_13_Distance,command_data_block[1])MOVE(Segment_13_TargetVelocity,command_data_block[2])MOVE(Segment_13_Acceleration_Deceleration,command_data_block[3]);
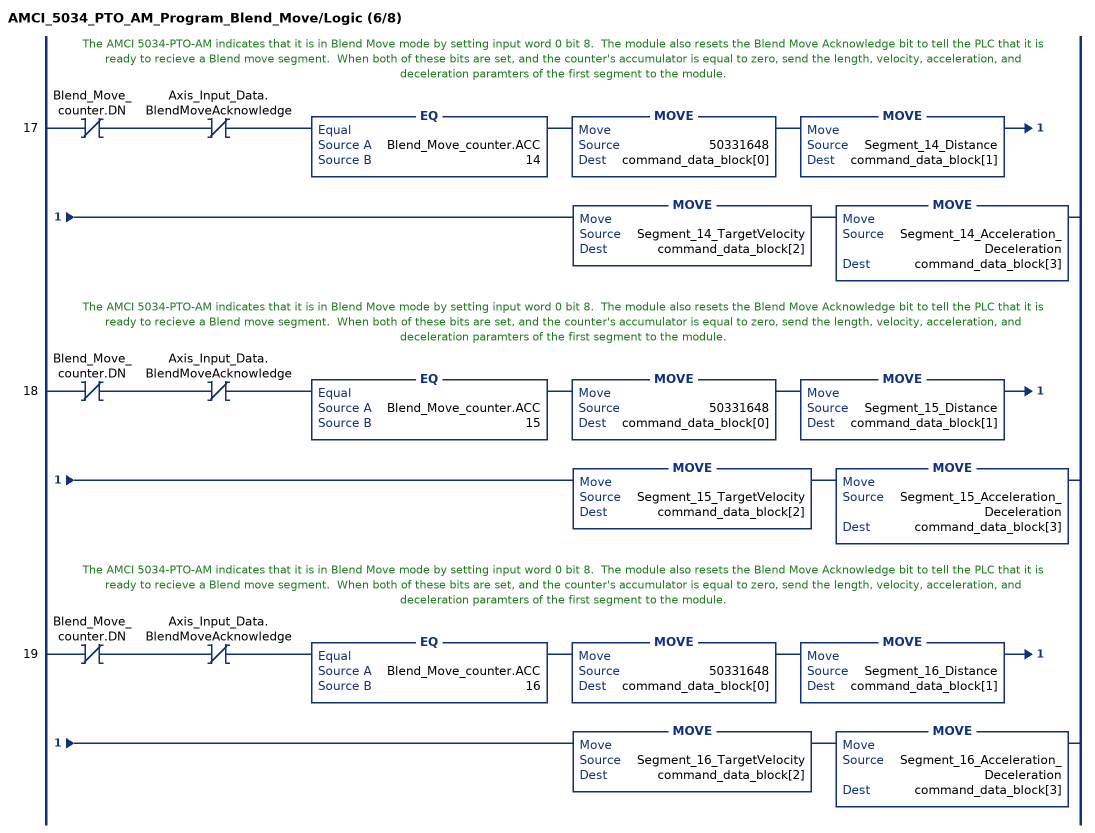
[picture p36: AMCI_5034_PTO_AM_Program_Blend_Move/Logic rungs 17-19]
   // The AMCI 5034-PTO-AM indicates that it is in Blend Move mode by setting input word 0 bit 8.  The module also resets the Blend Move Acknowledge bit to tell the PLC that it is ready to recieve a Blend move segment.  When both of these bits are set, and the counter's accumulator is equal to zero, send the length, velocity, acceleration, and deceleration paramters of the first segment to the module.
   17: XIO(Blend_Move_counter.DN)XIO(Axis_Input_Data.BlendMoveAcknowledge)EQ(Blend_Move_counter.ACC,14)MOVE(50331648,command_data_block[0])MOVE(Segment_14_Distance,command_data_block[1])MOVE(Segment_14_TargetVelocity,command_data_block[2])MOVE(Segment_14_Acceleration_Deceleration,command_data_block[3]);
   // The AMCI 5034-PTO-AM indicates that it is in Blend Move mode by setting input word 0 bit 8.  The module also resets the Blend Move Acknowledge bit to tell the PLC that it is ready to recieve a Blend move segment.  When both of these bits are set, and the counter's accumulator is equal to zero, send the length, velocity, acceleration, and deceleration paramters of the first segment to the module.
   18: XIO(Blend_Move_counter.DN)XIO(Axis_Input_Data.BlendMoveAcknowledge)EQ(Blend_Move_counter.ACC,15)MOVE(50331648,command_data_block[0])MOVE(Segment_15_Distance,command_data_block[1])MOVE(Segment_15_TargetVelocity,command_data_block[2])MOVE(Segment_15_Acceleration_Deceleration,command_data_block[3]);
   // The AMCI 5034-PTO-AM indicates that it is in Blend Move mode by setting input word 0 bit 8.  The module also resets the Blend Move Acknowledge bit to tell the PLC that it is ready to recieve a Blend move segment.  When both of these bits are set, and the counter's accumulator is equal to zero, send the length, velocity, acceleration, and deceleration paramters of the first segment to the module.
   19: XIO(Blend_Move_counter.DN)XIO(Axis_Input_Data.BlendMoveAcknowledge)EQ(Blend_Move_counter.ACC,16)MOVE(50331648,command_data_block[0])MOVE(Segment_16_Distance,command_data_block[1])MOVE(Segment_16_TargetVelocity,command_data_block[2])MOVE(Segment_16_Acceleration_Deceleration,command_data_block[3]);
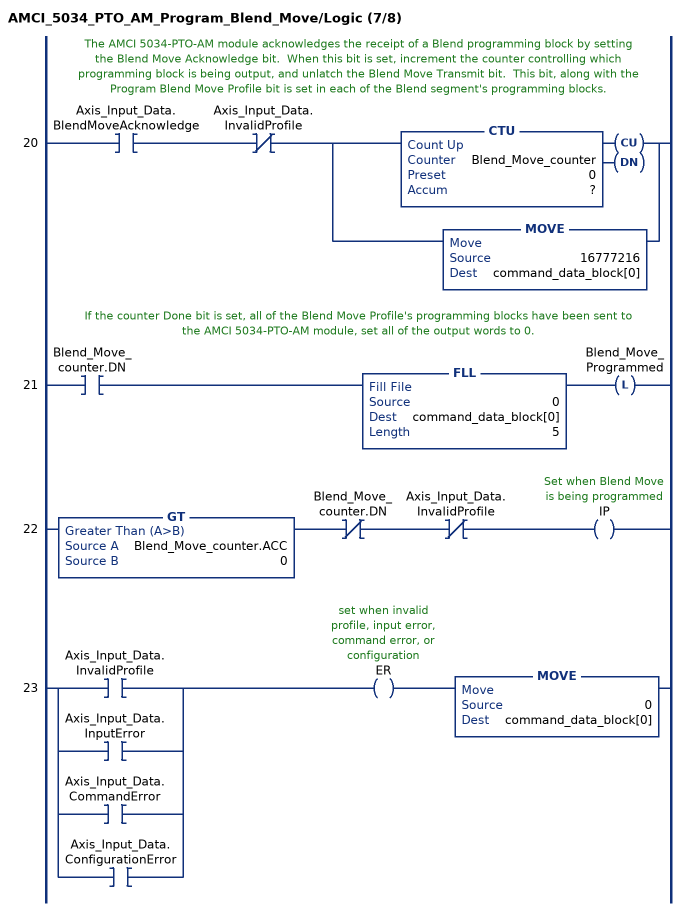
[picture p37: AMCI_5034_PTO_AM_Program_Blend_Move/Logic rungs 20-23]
   // The AMCI 5034-PTO-AM module acknowledges the receipt of a Blend programming block by setting the Blend Move Acknowledge bit.  When this bit is set, increment the counter controlling which programming block is being output, and unlatch the Blend Move Transmit bit.  This bit, along with the Program Blend Move Profile bit is set in each of the Blend segment's programming blocks.
   20: XIC(Axis_Input_Data.BlendMoveAcknowledge)XIO(Axis_Input_Data.InvalidProfile)[CTU(Blend_Move_counter,?,?) ,MOVE(16777216,command_data_block[0]) ];
   // If the counter Done bit is set, all of the Blend Move Profile's programming blocks have been sent to the AMCI 5034-PTO-AM module, set all of the output words to 0.
   21: XIC(Blend_Move_counter.DN)FLL(0,command_data_block[0],5)OTL(Blend_Move_Programmed);
   22: GT(Blend_Move_counter.ACC,0)XIO(Blend_Move_counter.DN)XIO(Axis_Input_Data.InvalidProfile)OTE(IP);
   23: [XIC(Axis_Input_Data.InvalidProfile) ,XIC(Axis_Input_Data.InputError) ,XIC(Axis_Input_Data.CommandError) ,XIC(Axis_Input_Data.ConfigurationError) ]OTE(ER)MOVE(0,command_data_block[0]);
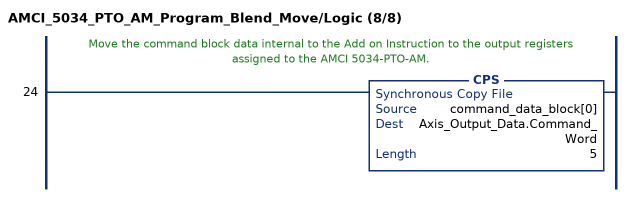
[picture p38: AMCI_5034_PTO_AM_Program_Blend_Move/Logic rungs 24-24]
   // Move the command block data internal to the Add on Instruction to the output registers assigned to the AMCI 5034-PTO-AM.
   24: CPS(command_data_block[0],Axis_Output_Data.Command_Word,5);
END_ROUTINE
END_ADD_ON_INSTRUCTION
